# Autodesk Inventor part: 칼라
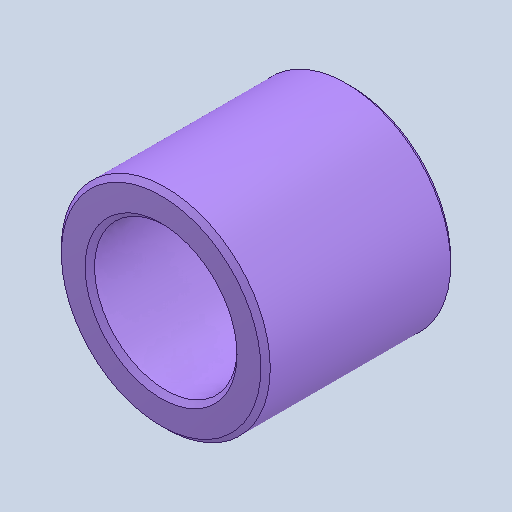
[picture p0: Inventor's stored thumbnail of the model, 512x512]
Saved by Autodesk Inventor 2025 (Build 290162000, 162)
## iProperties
Created: 2024-07
Part Number: 칼라
Material: 스테인리스강
Document SubType Name: Modeling
Designer: parkm
Density: 8.08 g/cm^3
Appearance: 기본값
Author: jhkim
Sending System: Autodesk Inventor 2025
Preprocessor: ST-DEVELOPER v20
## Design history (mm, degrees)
feature "솔리드1"
node "솔리드2"
